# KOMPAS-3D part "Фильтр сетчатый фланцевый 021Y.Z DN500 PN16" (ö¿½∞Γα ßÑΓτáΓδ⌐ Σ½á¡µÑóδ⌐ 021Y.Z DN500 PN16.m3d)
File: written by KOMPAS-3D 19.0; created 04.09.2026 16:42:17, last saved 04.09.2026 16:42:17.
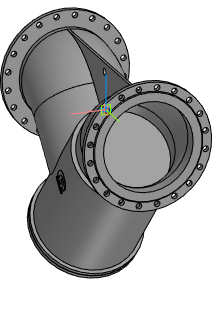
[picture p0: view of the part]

Document properties: Автор: Энергия; Полное имя файла: Z:\3.Личные\sachek\Dendor\_3D для проектировщиков\8.1 Фильтр сетчатый 021Y.Z\021Y.Z_STP\Фильтр сетчатый фланцевый 021Y.Z DN500 PN16.m3d

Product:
- Part/product: Фильтр сетчатый фланцевый 021Y.Z DN500 PN16

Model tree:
1. Операция без истории:1  (labels: Фильтр сетчатый фланцевый 021Y.Z DN500 PN16)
